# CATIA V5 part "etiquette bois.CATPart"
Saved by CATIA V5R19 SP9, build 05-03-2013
Part number: etiquette bois
Bounding box of the stored display mesh (mm): x -4.8 to 46.5, y -17 to 17, z -1.5 to 0
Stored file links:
  C:\Users\herve.bezard\Downloads\etiquette Soline\etiquette bois.CATPart
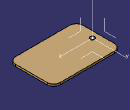
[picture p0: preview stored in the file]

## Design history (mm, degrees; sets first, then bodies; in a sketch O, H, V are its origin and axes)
AxisSystem1: origin (0, 0, 0), X (1, 0, 0), Y (0, 1, 0), Z (0, 0, 1)
Body1 (main body)
  Sketch1 on XY plane of AxisSystem1, origin (0, 0, 0), H (1, 0, 0), V (0, 1, 0)
    circle A1 centre (0, 0) radius 1.8
    point P1 (20.85, 0)
    line L1 (46.5, 12) -> (46.5, -12)
    line L2 (41.5, -17) -> (0.2, -17)
    line L3 (-4.8, -12) -> (-4.8, 12)
    line L4 (0.2, 17) -> (41.5, 17)
    arc A2 centre (41.5, 12) radius 5 from (46.5, 12) to (41.5, 17) ccw
    arc A3 centre (0.2, 12) radius 5 from (0.2, 17) to (-4.8, 12) ccw
    arc A4 centre (0.2, -12) radius 5 from (0.2, -17) to (-4.8, -12) cw
    arc A5 centre (41.5, -12) radius 5 from (41.5, -17) to (46.5, -12) ccw
    distance L4 L2 = 34
    distance L1 L3 = 51.3
    radius A1 = 1.8
    distance A1 L3 = 3
    radius A2 = 5
    radius A3 = 5
    radius A4 = 5
    radius A5 = 5
    coincidence: P1 H
    vertical: L1 V, L3 V
    horizontal: L2 H, L4 H
    equidistance: L1 L3 P1, L2 L4 P1
    tangency: A2 L1, A2 L4, A3 L4, A3 L3, A4 L2, A4 L3, A5 L2, A5 L1
  Pad1: profile Sketch1, direction (0, 0, -1), length 1.5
